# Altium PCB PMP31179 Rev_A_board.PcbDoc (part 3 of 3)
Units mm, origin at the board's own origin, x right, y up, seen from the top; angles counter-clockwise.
Board outline 218.44 x 102.26 mm, 4 copper layers (Top Layer, Mid-Layer 1, Mid-Layer 2, Bottom Layer), stack 1.473 mm thick; 246 components, 120 nets, 592 pads, 115 vias.
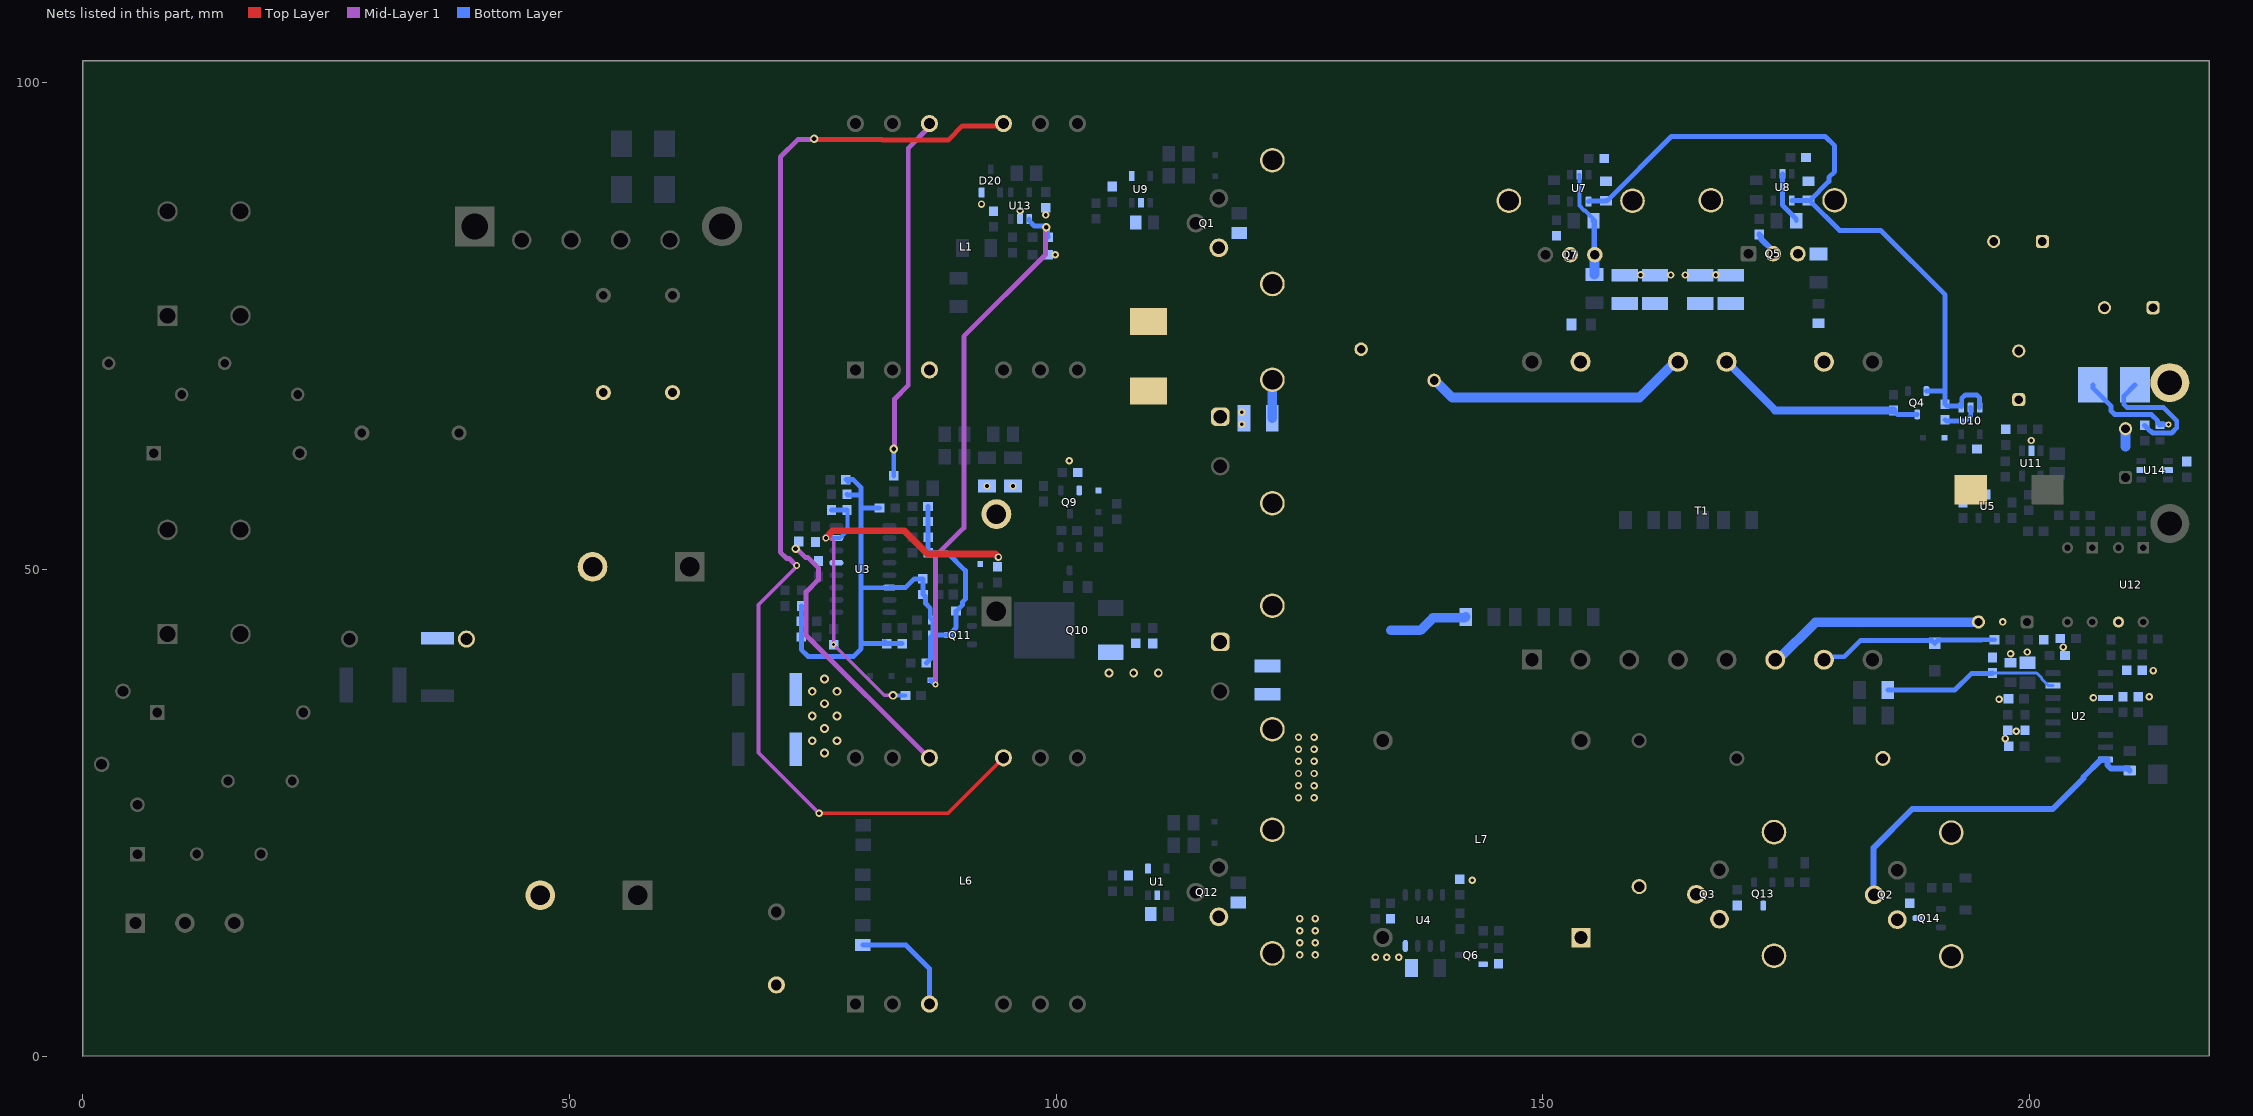
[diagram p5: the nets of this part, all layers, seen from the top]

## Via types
v1: diameter 0.762, hole 0.381, Top Layer to Bottom Layer, 47 vias
v2: diameter 0.9, hole 0.5, Top Layer to Bottom Layer, 18 vias
v3: diameter 0.762, hole 0.381, Top Layer to Bottom Layer, tented bottom, 17 vias
v4: diameter 0.9, hole 0.5, Top Layer to Bottom Layer, tented bottom, 7 vias
v5: diameter 0.6, hole 0.3, Top Layer to Bottom Layer, tented bottom, 5 vias
v6: diameter 0.762, hole 0.381, Top Layer to Bottom Layer, tented both sides, 5 vias
v7: diameter 0.9, hole 0.5, Top Layer to Bottom Layer, tented top, 4 vias
v8: diameter 0.7, hole 0.4, Top Layer to Bottom Layer, tented bottom, 4 vias
v9: diameter 0.6, hole 0.3, Top Layer to Bottom Layer, 4 vias
v10: diameter 0.7, hole 0.4, Top Layer to Bottom Layer, tented top, 1 vias
v11: diameter 0.9, hole 0.5, Top Layer to Bottom Layer, tented both sides, 1 vias
v12: diameter 0.7/0.7/0.7/0.7 (per signal layer), hole 0.4, Top Layer to Bottom Layer, 1 vias
v13: diameter 0.762, hole 0.381, Top Layer to Bottom Layer, tented top, 1 vias

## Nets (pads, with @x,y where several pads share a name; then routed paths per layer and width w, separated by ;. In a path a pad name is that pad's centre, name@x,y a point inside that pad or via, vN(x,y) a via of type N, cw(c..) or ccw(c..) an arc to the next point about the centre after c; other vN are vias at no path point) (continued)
PGND: C3.2 C7.2 C8.2 C15.2 C16.2 C17.2 C18.2 C19.2 C20.2 C21.2 C22.2 C23.2 C24.2 C25.2 C27.2 C28.2 C29.2 C30.1 C31.2 C32.2 C33.2 C34.2 C35.1 C36.2 C37.2 C38.2 C41.2 C43.2 C51.2 C52.2 C58.2 C59.2 C60.2 C62.2 C63.2 C65.2 D14.2 D20.2 L1.9 L6.9 M1.1 M1.2 M2.1 M2.2 M3.1 M3.2 M4.1 M4.2 M5.1 M5.2 M6.1 M6.2 Q1.3 Q2.3 Q6.2 Q9.2 Q10.3 Q11.3 Q12.3 Q14.3 R1.1 R2.1 R3.1 R6.1 R7.1 R8.1 R11.1 R12.1 R14.2 R18.1 R19.1 R32.1 R35.1 R41.2 R45.1 R55.1 R64.1 R76.1 R82.1 R88.2 R89.1 R90.1 RT1.1 T1.6 U1.2 U1.4 U2.11 U3.6 U3.13 U4.4 U9.2 U9.4 U12.3 U13.2 | length 217.7
  Top Layer w0.381: v1(75.634,24.972) 88.883,24.972 L6.9@94.575,30.664
  Top Layer w0.5: v7(75.131,94.256) 75.207,94.179 82.111,94.179 82.14,94.149 88.935,94.149 90.362,95.576 94.336,95.576 L1.9@94.575,95.815
  Mid-Layer 1 w0.381: v12(73.343,50.407) 73.343,50.32 69.422,46.4 69.422,42.294 69.422,31.184 v1(75.634,24.972)
  Mid-Layer 1 w0.5: v12(73.343,50.407) 73.289,50.407 72.543,51.152 72.291,51.152 71.665,51.778 71.665,92.385 73.459,94.179 75.054,94.179 v7(75.131,94.256)
  Bottom Layer w0.381: L6.9@94.205,30.664 L6.9@94.575,30.664
  Bottom Layer w0.5: C29.2@73.818,46.271 73.808,46.261 73.808,44.694 C37.2@73.797,44.684 R11.1@73.797,43.087 73.818,43.067 73.818,41.767 74.498,41.087 79.176,41.087 79.951,41.862 79.951,42.64 ; R41.2@78.386,59.238 R41.2@78.411,59.238 ; C38.2@78.499,57.734 78.56,57.672 79.951,57.672 ; R41.2@78.636,58.988 78.636,59.013 R41.2@78.411,59.238 ; C25.2@81.851,56.316 79.951,56.316 ; C43.2@82.36,42.64 82.585,42.415 C43.2@82.585,42.39 ; R90.1@84.176,42.39 C43.2@82.585,42.39 ; R18.1@86.652,40.416 86.677,40.416 87.067,40.806 87.067,43.04 87.292,43.265 C41.2@87.317,43.265 ; R35.1@86.828,56.469 C33.2@86.828,54.945 86.835,54.938 86.835,53.339 R89.1@86.842,53.332 C21.2@86.842,51.731 86.846,51.735 88.825,51.735 90.66,49.9 90.66,46.966 90.351,46.657 90.351,46.355 89.73,45.733 C15.2@89.705,45.733 89.705,44.032 89.192,43.519 89.192,43.319 89.142,43.269 Q11.3@88.942,43.269 88.94,43.267 87.319,43.267 C41.2@87.317,43.265 ; R41.2@78.411,59.238 79.136,59.238 79.951,58.422 79.951,57.672 ; 79.951,42.64 80.201,42.39 C43.2@82.585,42.39 ; 79.951,42.64 79.951,48.002 ; 79.951,48.002 80.085,48.136 82.843,48.136 U3.6@82.862,48.155 82.881,48.174 84.54,48.174 85.417,49.052 C34.2@86.284,49.052 86.299,49.037 86.299,47.467 C36.2@86.314,47.452 86.339,47.452 86.564,47.227 86.564,46.524 87.053,46.035 87.053,45.035 87.278,44.81 R88.2@87.303,44.81 87.31,44.803 87.31,43.272 C41.2@87.317,43.265 ; 79.951,48.002 79.951,56.316 ; 79.951,56.316 79.951,57.672
  Bottom Layer w1: C7.2@122.196,65.553 122.201,65.557 122.201,69.503 M6.1@122.205,69.508 ; T1.6@173.864,40.744 174.148,40.744 177.981,44.577 C60.2@194.694,44.577 ; C60.2@194.671,44.554 C60.2@194.694,44.577 ; C60.2@194.738,44.621 C60.2@194.694,44.577
  other v1: 132.788,10.187 133.954,10.187 135.173,10.187 125.019,10.414 126.619,10.414 125.019,11.659 126.619,11.659 125.019,12.903 126.619,12.903 125.019,14.148 126.619,14.148 142.742,18.08 124.886,26.564 126.486,26.564 124.886,27.808 126.486,27.808 124.886,29.053 126.486,29.053 124.886,30.297 126.486,30.297 124.886,31.542 126.486,31.542 124.886,32.787 126.486,32.787 197.238,44.621 101.341,61.176
  other v2: 74.93,32.415 76.2,33.685 74.93,34.955 77.47,34.955 76.2,36.225 74.93,37.495 77.47,37.495 76.2,38.765 105.41,39.37 107.95,39.37 110.49,39.37
  other v3: 197.485,32.639 198.628,33.401 196.855,36.684 206.548,36.823 212.287,36.934 212.681,39.628 198.04,41.341 199.76,41.532 203.454,42.037 99.904,82.331
  other v6: 98.922,86.434 96.28,86.852 92.325,87.549
  other v7: 76.2,31.145 77.47,32.415
R_SENSE: pad.1@214.397,69.208 R65.2 R66.1 | length 13.2
  Bottom Layer w0.5: R65.2@210.817,68.98 209.665,67.828 209.665,66.979 210.005,66.639 213.775,66.639 215.108,65.306 215.108,64.564 214.571,64.027 212.663,64.027 212.51,64.18 212.434,64.18 211.812,64.802 R66.1@211.812,64.827
SGND: C12.2 C13.2 C14.2 C44.1 C45.1 C46.2 C48.2 C53.2 C54.2 C55.2 C56.2 C57.2 C67.2 C68.2 C72.2 C73.2 C76.2 C100.2 C101.2 D4.2 M7.1 M7.2 M8.1 M8.2 Q5.3 Q7.3 R50.1 R65.1 R72.1 R78.1 U5.3 U7.2 U8.2 U10.2 U11.2 U14.2 U14.5 | length 32.1
  Bottom Layer w0.4: U7.2@153.723,90.557 153.737,90.543 153.737,87.402 154.235,86.904 154.307,86.904 155.194,86.017 C100.2@155.194,85.852
  Bottom Layer w0.5: U8.2@174.609,90.663 174.609,87.43 176.022,86.017 C101.2@176.022,85.852 ; C55.2@191.309,65.396 191.431,65.274 193.429,65.274 193.944,65.789 193.944,66.634 U10.2@193.929,66.649 ; R65.1@206.497,68.98 206.497,68.665 208.37,66.792 208.37,66.29 208.723,65.936 212.511,65.936 213.163,65.284 213.163,65.052 R78.1@213.388,64.827 213.473,64.912 214.234,64.912 v5(214.249,64.897)
  Bottom Layer w0.6: C100.2@155.194,85.852 155.263,85.783 155.263,82.421 Q7.3@155.333,82.352
  Bottom Layer w1: C45.1@155.276,80.309 155.304,80.337 155.304,82.323 Q7.3@155.333,82.352 ; 209.851,62.626 C76.2@209.851,64.469
  other v1: 200.173,63.262 160.026,80.27 163.138,80.267 164.611,80.267 167.761,80.27
SW: C26.2 L7.1 Q2.2 Q3.3 Q13.3 R44.1 U2.16 | length 35.8
  Bottom Layer w0.6: Q2.2@184.038,16.583 183.973,16.648 183.973,21.429 187.94,25.396 202.362,25.396 205.531,28.565 205.531,28.694 207.311,30.473 U2.16@207.786,30.473 207.98,30.473 207.98,29.918 208.343,29.556 210.087,29.556 C26.2@210.287,29.356
UVLO: D15.1 R75.2 U13.1 | length 55.7
  Mid-Layer 1 w0.5: v9(87.587,38.183) 87.587,51.366 90.505,54.283 90.505,73.969 98.895,82.36 98.895,85.096 v11(98.972,85.173)
  Bottom Layer w0.5: D15.1@87.079,38.638 87.515,38.202 87.568,38.202 v9(87.587,38.183) ; U13.1@97.23,86.025 97.23,85.825 97.755,85.3 98.844,85.3 v11(98.972,85.173) 99.099,85.045 99.099,84.209 R75.2@99.154,84.154
V30V: C8.1 C12.1 C13.1 C14.1 C67.1 C68.1 C72.1 C73.1 L4.1 Q4.3 R62.2 T1.12 T1.13 | length 49.1
  Bottom Layer w0.5: R62.2@186.012,66.354 186.012,66.329 186.237,66.104 186.262,66.104 186.43,65.936 Q4.3@188.451,65.936
  Bottom Layer w0.8: T1.12@168.864,71.344 T1.12@168.864,71.344 173.852,66.354 R62.2@186.012,66.354
  Bottom Layer w1: C8.1@138.821,69.439 138.929,69.439 140.677,67.691 159.927,67.691 163.58,71.344 T1.13@163.864,71.344
VAC: C5.1 C61.1 D100.2 L1.3 L2.2 L6.3 R23.2 R91.2 | length 11.5
  Bottom Layer w0.5: R23.2@80.137,11.43 84.549,11.43 86.975,9.004 L6.3@86.975,5.364
VCR: C22.1 C40.2 U2.7 | length 18.3
  Bottom Layer w0.3: C22.1@196.182,39.378 196.186,39.382 200.72,39.382 201.241,38.861 201.241,38.764 201.911,38.093 U2.7@202.386,38.093
  Bottom Layer w0.5: C40.2@185.423,37.638 192.333,37.638 194.009,39.315 196.119,39.315 C22.1@196.182,39.378
VD1: Q7.2 R53.1 R100.2 T1.15 | length 0.3
  Bottom Layer w0.5: Q7.2@152.793,82.352 Q7.2@152.793,82.649
VD2: Q5.2 R52.1 R101.2 T1.10 | length 2.6
  Bottom Layer w0.6: R101.2@172.212,84.417 172.387,84.242 172.387,83.988 173.652,82.722 Q5.2@173.652,82.452
VDD: C46.1 C48.1 C55.1 Q4.2 U7.4 U8.4 U10.1 U10.3 | length 73.7
  Bottom Layer w0.5: U7.4@154.673,87.807 154.719,87.854 156.418,87.854 C46.1@156.464,87.9 156.589,87.9 163.177,94.488 178.995,94.488 179.959,93.524 179.959,90.868 179.377,90.287 179.377,89.883 C48.1@177.401,87.907 ; U8.4@175.559,87.913 175.562,87.91 177.273,87.91 C48.1@177.276,87.907 C48.1@177.401,87.907 ; Q4.2@189.401,68.336 189.418,68.354 191.291,68.354 191.309,68.336 ; U10.3@194.879,66.649 194.865,66.663 194.865,67.643 194.572,67.936 193.379,67.936 193.029,67.586 193.029,66.823 192.979,66.773 192.929,66.823 191.483,66.823 C55.1@191.309,66.996 191.309,68.336 ; C48.1@177.401,87.907 180.464,84.844 184.681,84.844 191.309,78.216 191.309,68.336
Vpfc: C1A.2 C1B.2 C1C.2 C2.1 C7.1 C65.1 D1.1 D5.1 D100.1 Q3.2 R20.2 R43.2 R87.2 | length 8.3
  Bottom Layer w1: 134.359,43.761 137.4,43.761 138.689,45.05 141.971,45.05 R43.2@142.066,45.145
  other v1: 92.888,58.583 95.555,58.583 119.046,64.921 119.046,66.173
VREF: C38.1 D2.1 R15.1 R16.2 R37.2 R39.2 U3.15 | length 46.6
  Top Layer w0.7: v8(76.327,53.243) 77.076,53.992 84.363,53.992 86.759,51.596 93.745,51.596 94.059,51.283 v3(94.063,51.283)
  Mid-Layer 1 w0.381: v8(76.327,53.243) 76.331,53.239 76.869,53.239 77.135,52.973 v9(77.135,42.287) 82.339,37.084 v4(83.219,37.084)
  Bottom Layer w0.381: v8(76.327,53.243) 76.331,53.239 77.408,53.239 U3.15@77.412,53.235 ; v4(83.219,37.084) 83.233,37.07 84.488,37.07 R16.2@84.502,37.056
  Bottom Layer w0.4: U3.15@77.412,53.235 77.783,53.235 78.54,53.992 78.54,56.093 C38.1@78.499,56.134
  Bottom Layer w0.5: R39.2@76.899,56.134 C38.1@78.499,56.134
X: D11.2 R9.2 T1.7 | length 18.6
  Bottom Layer w0.5: T1.7@178.864,40.744 179.161,41.04 180.936,41.04 182.602,42.706 189.961,42.706 D11.2@190.246,42.421 190.596,42.771 195.073,42.771 195.096,42.794 R9.2@196.398,42.794
ZCD_A: L6.10 R24.2 | length 28.6
  Mid-Layer 1 w0.5: v4@73.139,52.137 73.337,52.137 74.218,51.256 74.477,51.256 75.565,50.168 75.565,48.943 74.293,47.671 74.293,43.261 86.89,30.664 L6.10@86.975,30.664
  other v4: 73.229,52.137
ZCD_B: L1.10 R26.2 | length 37.7
  Mid-Layer 1 w0.5: v2(83.306,62.383) 83.383,62.46 83.383,67.512 84.801,68.93 84.801,93.302 86.975,95.476 L1.10@86.975,95.815
  Bottom Layer w0.5: v2(83.306,62.383) 83.308,62.382 83.308,59.635 R26.2@83.31,59.633
pads on no net: D20.3 H1.0 H2.0 H3.0 H4.0 H5.0 H6.0 H7.1 H7.2 L1.1 L1.2 L1.5 L1.6 L1.7 L1.8 L1.11 L1.12 L6.1 L6.2 L6.5 L6.6 L6.7 L6.8 L6.11 L6.12 L7.7 L7.14 T1.1 T1.8 T1.9 T1.16 U4.2 U4.5 U4.6 U10.4

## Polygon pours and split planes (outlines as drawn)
V30V on Top Layer "TOP_LAYER_V30V_P064" (solid, remove dead copper, pour order 64): 161.794,73.431 170.408,73.431 173.959,69.88 206.49,69.88 210.651,74.041 210.651,79.063 208.688,81.026 200.256,81.026 199.105,82.177 199.105,96.108 202.057,99.06 214.884,99.06 216.789,97.155 216.789,72.662 216.015,71.889 213.545,71.889 211.957,70.3 211.957,67.746 209.116,64.905 199.744,64.905 195.938,61.099 195.938,56.837 195.228,56.127 189.498,56.127 188.079,57.546 173.309,57.546 161.794,69.061
SGND on Top Layer "TOP_LAYER_SGND_P063" (solid, remove dead copper, pour order 63): 142.24,78.826 169.616,78.826 177.273,71.169 205.732,71.169 208.858,74.295 208.858,78.466 208.039,79.285 199.043,79.285 197.851,80.477 197.851,96.058 194.848,99.06 145.923,99.06 142.24,95.377
30V on Top Layer "TOP_LAYER_30V_P059" (solid, remove dead copper, pour order 59): 216.015,51.181 201.214,51.181 200.154,52.241 200.154,60.019 200.729,60.594 216.026,60.594 216.789,59.831 216.789,51.955
PGND on Top Layer "TOP_LAYER_PGND_P042" (solid, remove dead copper, pour order 42): 133.604,75.591 132.275,74.262 132.275,67.163 133.604,65.834 133.604,32.425 138.221,27.808 178.568,27.808 182.614,31.854 186.138,31.854 187.437,30.556 188.403,30.556 190.86,28.098 197.299,28.098 199.665,25.732 199.665,4.046 197.529,1.909 116.101,1.905 116.101,15.203 116.495,15.598 119.809,15.598 120.858,16.648 120.858,45.572 119.445,46.986 116.123,46.986 114.831,48.278 114.831,56.008 116.382,57.559 121.406,57.559 121.406,77.23 115.695,82.941 115.695,83.555 116.625,84.484 121.485,84.484 121.485,99.06 130.937,99.06 133.604,96.393
PGND on Top Layer "TOP_LAYER_PGND_P039" (solid, remove dead copper, pour order 39): 183.763,29.465 199.371,29.465 201.784,27.052 201.784,4.875 204.089,2.57 213.274,2.57 216.916,6.212 216.916,44.579 216.059,45.436 184.501,45.436 183.763,44.698
VAC on Top Layer "TOP_LAYER_VAC_P019" (solid, remove dead copper, pour order 19): 111.379,73.182 94.768,73.182 88.687,67.1 87.818,67.1 85.299,69.619 85.299,76.921 88.276,79.897 109.947,79.897 111.379,78.465
Vpfc on Top Layer "TOP_LAYER_VPFC_P018" (solid, remove dead copper, pour order 18): 80.476,61.1 87.491,61.1 96.327,69.935 117.86,69.935 119.855,67.94 119.855,64.558 118.455,63.158 114.831,63.158 112.44,60.767 112.44,47.078 114.355,45.163 117.66,45.163 119.046,43.777 119.046,41.506 117.727,40.188 114.014,40.188 106.299,40.188 105.122,41.365 105.122,46.887 98.905,53.104 87.428,53.104 83.935,56.596 80.412,56.596
Vpfc on Top Layer "TOP_LAYER_VPFC_P017" (solid, remove dead copper, pour order 17): 51.501,14.73 53.213,16.442 53.213,23.398 56.134,26.319 56.134,51.726 59.62,55.212 84.237,55.212 86.369,53.081 98.353,53.081 99.415,54.142 99.415,59.751 98.065,61.1 59.373,61.1 45.37,47.097 45.37,15.842 46.482,14.73
NetC1A_1 on Top Layer "TOP_LAYER_NETC1A_1_P015" (solid, remove dead copper, pour order 15): 54.737,21.366 58.166,24.795 58.166,50.743 60.579,53.081 82.415,53.081 85.306,50.19 99.459,50.19 102.399,47.25 102.399,41.133 99.322,38.056 83.09,38.056 75.005,29.97 75.107,14.096 55.656,14.096 54.737,15.016
VAC on Top Layer "TOP_LAYER_VAC_P011" (solid, remove dead copper, pour order 11): 75.563,72.19 75.563,79.882 87.847,79.882 89.527,78.201 89.645,73.694 89.645,67.439 85.227,63.022 59.361,63.022 43.18,46.841 43.18,16.54 46.228,13.492 87.349,13.492 90.551,10.29 90.551,5.999 86.614,2.062 39.116,2.062 30.89,10.287 30.89,53.145 49.936,72.19
NetC10_2 on Top Layer "TOP_LAYER_NETC10_2_P005" (solid, remove dead copper, pour order 5): 13.259,51.984 18.307,51.984 24.037,57.714 24.037,75.348 20.542,78.842 14.313,78.842 12.827,77.356 12.827,75.334 15.791,72.37 15.791,65.143 13.259,62.612
NetC10_1 on Top Layer "TOP_LAYER_NETC10_1_P004" (solid, remove dead copper, pour order 4): 11.207,51.984 5.76,51.984 1.473,56.272 1.473,75.87 4.445,78.842 9.622,78.842 10.711,77.754 10.711,73.956 7.864,71.109 7.864,65.714 11.207,62.371
NetC9_2 on Top Layer "TOP_LAYER_NETC9_2_P002" (solid, remove dead copper, pour order 2): 17.593,27.507 13.208,23.122 13.274,20.416 8.509,15.651 8.509,12.473 9.268,11.714 10.803,11.714 16.793,17.704 16.793,20.757 24.138,28.102 24.138,43.865 16.793,51.211 2.216,51.211 0.946,49.941 0.946,36.88 2,35.826 5.173,35.826 6.207,36.86 6.207,46.104 6.858,46.755 10.093,46.755 17.593,39.255
NetC6_1 on Top Layer "TOP_LAYER_NETC6_1_P001" (solid, remove dead copper, pour order 1): 1.079,26.763 2.921,24.922 7.508,24.922 12.349,29.763 12.349,42.321 9.343,45.327 7.684,45.327 7.176,44.819 7.176,36.484 1.079,30.388
NetF1_1 on Top Layer "TOP_LAYER_NETF1_1_P000" (solid, remove dead copper, pour order 0): 6.604,11.714 3.81,11.714 2.159,13.365 2.159,21.239 3.175,22.255 6.858,22.255 7.493,21.62 7.493,12.603
SGND on Mid-Layer 2 "MID-LAYER_2_SGND_P044" (solid, remove dead copper, pour order 44): 187.374,58.21 187.374,61.24 184.132,64.473 184.132,69.909 201.57,69.909 208.352,63.128 210.446,63.128 211.45,62.123 211.45,61.917 216.789,61.917 216.789,51.955 216.015,51.181 190.5,51.181 189.736,51.945 189.736,55.848
SGND on Mid-Layer 2 "MID-LAYER_2_SGND_P057" (solid, remove dead copper, pour order 57): 202.484,71.12 209.705,63.899 215.528,63.899 216.789,65.16 216.789,95.25 212.979,99.06 147.986,99.06 143.681,94.755 143.7,62.897 180.367,62.897 182.021,64.551 182.021,69.88 183.261,71.12
PGND on Mid-Layer 2 "MID-LAYER_2_PGND_P014" (solid, remove dead copper, pour order 14): 133.731,75.596 132.123,73.988 132.085,73.988 132.085,67.353 133.731,65.834 133.731,61.244 146.487,48.488 181.428,48.488 182.614,47.302 182.614,36.089 191.023,27.679 198.964,27.679 201.278,25.365 201.278,6.446 197.529,2.697 32.766,2.697 26.289,9.174 26.289,92.232 33.274,99.217 130.699,99.217 133.731,96.185
PGND on Mid-Layer 2 "MID-LAYER_2_PGND_P038" (solid, remove dead copper, pour order 38): 183.763,29.465 199.371,29.465 201.784,27.052 201.784,4.875 204.089,2.57 213.274,2.57 216.916,6.212 216.916,44.579 216.059,45.436 184.501,45.436 183.763,44.698
EARTH on Mid-Layer 2 "MID-LAYER_2_EARTH_P003" (solid, remove dead copper, pour order 3): 1.171,11.714 1.171,79.16 24.13,79.16 24.13,11.714
Vpfc on Bottom Layer "BOTTOM_LAYER_VPFC_P066" (solid, remove dead copper, pour order 66): 115.906,63.928 120.028,63.928 120.163,64.064 120.163,66.983 119.855,67.291 115.892,67.291 115.606,67.005 115.606,64.228
PGND on Bottom Layer "BOTTOM_LAYER_PGND_P065" (solid, remove dead copper, pour order 65): 120.015,37.973 123.544,37.973 126.956,34.561 126.956,31.333 126.415,30.792 120.846,30.792 120.015,31.623
SGND on Bottom Layer "BOTTOM_LAYER_SGND_P062" (solid, remove dead copper, pour order 62): 210.754,63.705 209.564,63.705 202.149,71.12 196.728,71.12 194.879,72.969 194.879,95.443 194.818,95.504 198.374,99.06 206.011,99.06 208.957,96.114 208.957,71.685 208.039,70.768 208.039,67.246 209.349,65.936 210.824,65.936
R_SENSE on Bottom Layer "BOTTOM_LAYER_R_SENSE_P060" (solid, remove dead copper, pour order 60): 209.296,67.183 215.506,67.183 216.614,68.29 216.614,70.218 215.407,71.425 209.296,71.425
SGND on Bottom Layer "BOTTOM_LAYER_SGND_P058" (solid, remove dead copper, pour order 58): 187.369,58.224 187.369,61.253 184.127,64.487 184.127,69.923 201.566,69.923 208.347,63.141 210.441,63.141 211.445,62.137 211.445,61.931 216.784,61.931 216.784,51.968 216.011,51.195 190.496,51.195 189.731,51.959 189.731,55.862
VD2 on Bottom Layer "BOTTOM_LAYER_VD2_P056" (solid, remove dead copper, pour order 56): 176.775,75.885 175.492,77.169 175.492,78.527 175.006,79.013 175.006,82.348 174.114,83.24 173.135,83.24 172.903,83.008 172.903,72.674 175.667,69.909 180.194,69.909 180.194,74.712 179.021,75.885
NetC44_2 on Bottom Layer "BOTTOM_LAYER_NETC44_2_P055" (solid, remove dead copper, pour order 55): 179.414,76.708 177.502,76.708 177.216,76.994 177.216,80.06 177.408,80.252 179.29,80.252 179.483,80.059 179.483,76.777
SGND on Bottom Layer "BOTTOM_LAYER_SGND_P054" (solid, remove dead copper, pour order 54): 176.543,91.255 176.519,91.279 176.519,92.806 177.741,92.806 178.297,92.249 178.364,90.95 178.612,90.702 178.612,89.118 177.983,88.489 175.138,88.489 175.138,87.501 175.492,87.148 176.7,87.148 176.7,84.353 177.174,83.88 178.93,83.88 179.483,83.327 179.483,81.47 175.785,81.47 175.414,81.841 175.414,84.639 174.109,85.944 174.109,91.142 174.356,91.388 175.109,91.388 175.109,90.357 175.376,90.089 176.009,90.089 176.009,90.722
SGND on Bottom Layer "BOTTOM_LAYER_SGND_P053" (solid, remove dead copper, pour order 53): 157.038,79.527 170.635,79.527 170.885,79.777 170.885,80.851 170.635,81.101 157.163,81.101 157.038,80.977
V30V on Bottom Layer "BOTTOM_LAYER_V30V_P052" (solid, remove dead copper, pour order 52): 157.038,78.074 157.038,73.988 161.117,69.909 169.932,69.909 170.853,70.831 170.853,78.041 170.885,78.074
SGND on Bottom Layer "BOTTOM_LAYER_SGND_P051" (solid, remove dead copper, pour order 51): 155.784,90.278 155.784,92.705 156.788,92.705 156.788,90.487 157.214,90.487 157.214,88.925 156.996,88.707 154.547,88.707 154.223,88.383 154.223,87.469 154.824,86.868 155.776,86.868 155.776,85.209 154.452,85.209 154.452,86.37 154.259,86.37 153.326,87.302 153.326,91.137 153.471,91.282 154.039,91.282 154.223,91.099 154.223,89.837 154.377,89.682 155.188,89.682
NetC100_1 on Bottom Layer "BOTTOM_LAYER_NETC100_1_P050" (solid, remove dead copper, pour order 50): 150.909,85.209 151.925,85.209 152.298,84.836 153.897,84.836 153.951,84.889 153.951,86.502 153.351,87.102 153.351,88.383 152.352,88.383 152.173,88.203 152.173,87.082 151.73,86.64 151.12,86.64 150.909,86.429
VD1 on Bottom Layer "BOTTOM_LAYER_VD1_P049" (solid, remove dead copper, pour order 49): 152.586,69.571 151.733,70.424 151.733,82.525 150.691,83.566 150.691,84.629 150.909,84.846 151.966,84.846 153.997,82.815 153.997,82.106 153.997,74.041 155.272,72.766 155.46,72.766 155.46,69.909 155.121,69.571
PGND on Bottom Layer "BOTTOM_LAYER_PGND_P041" (solid, remove dead copper, pour order 41): 183.89,29.216 196.301,29.216 198.616,31.531 198.616,36.258 187.771,36.258 183.842,32.329
PGND on Bottom Layer "BOTTOM_LAYER_PGND_P040" (solid, remove dead copper, pour order 40): 216.916,36.258 206.847,36.258 203.355,32.766 199.209,32.766 198.659,32.216 198.659,31.129 196.702,31.129 191.275,36.557 191.275,45.436 216.059,45.436 216.916,44.579
NetC2_2 on Bottom Layer "BOTTOM_LAYER_NETC2_2_P037" (solid, remove dead copper, pour order 37): 159.056,29.717 169.997,29.717 170.696,30.416 170.696,40.572 169.293,41.974 162.563,41.974 162.279,41.69 162.279,36.126 159.008,32.855
NetL7_6 on Bottom Layer "BOTTOM_LAYER_NETL7_6_P036" (solid, remove dead copper, pour order 36): 153.39,30.842 155.199,30.842 160.449,36.092 160.449,40.744 159.219,41.974 153.409,41.974 152.226,40.792 152.226,31.876 153.226,30.876
PGND on Bottom Layer "BOTTOM_LAYER_PGND_P035" (solid, remove dead copper, pour order 35): 187.94,12.744 189.006,13.811 189.006,15.695 188.4,16.302 186.849,16.302 185.462,14.915 185.203,14.656 185.203,13.601 186.06,12.744
SW on Bottom Layer "BOTTOM_LAYER_SW_P034" (solid, remove dead copper, pour order 34): 164.963,13.711 ccw(c164.963,16.251) 166.759,14.455 167.897,15.593 cw(c169.178,14.312) 169.178,16.124 180.414,16.124 ccw(c180.414,18.381) 182.01,16.785 183.034,17.809 cw(c183.689,17.154) 183.689,18.08 184.214,18.08 cw(c184.214,17.073) 185.222,17.073 cw(c182.855,17.073) 184.528,15.4 183.116,13.988 cw(c181.32,15.784) 181.32,13.244 169.828,13.244 ccw(c169.828,12.863) 169.559,13.132 167.812,11.386 cw(c166.016,13.182) 166.016,10.642 152.819,10.642 cw(c152.819,11.492) 151.969,11.492 151.969,12.135 cw(c153.545,12.135) 153.545,13.711
PGND on Bottom Layer "BOTTOM_LAYER_PGND_P033" (solid, remove dead copper, pour order 33): 134.602,19.399 126.956,19.399 120.685,13.129 120.685,8.316 123.667,5.334 134.874,5.334
PGND on Bottom Layer "BOTTOM_LAYER_PGND_P032" (solid, remove dead copper, pour order 32): 130.375,8.559 133.6,5.334 145.434,5.334 147.571,7.47 147.571,14.536 142.688,19.419 132.253,19.419 130.375,17.542
Vpfc on Bottom Layer "BOTTOM_LAYER_VPFC_P031" (solid, remove dead copper, pour order 31): 125.103,38.637 118.923,38.637 115.54,42.019 115.54,44.283 135.325,44.283 137.166,42.442 157.976,21.632 162.897,21.632 167.116,17.413 167.116,15.983 166.316,15.183 148.557,15.183
PGND on Bottom Layer "BOTTOM_LAYER_PGND_P030" (solid, remove dead copper, pour order 30): 105.033,94.149 89.604,94.149 84.644,89.189 84.644,75.703 86.652,73.694 100.275,73.694 105.046,78.465 105.033,78.478
PGND on Bottom Layer "BOTTOM_LAYER_PGND_P029" (solid, remove dead copper, pour order 29): 119.906,85.212 117.454,85.212 115.135,82.893 113.778,82.893 112.141,84.53 112.141,86.736 113.862,88.458 114.89,89.486 114.89,95.379 114.299,95.97 106.368,95.97 102.727,92.328 102.727,83.429 105.291,80.865 118.358,80.865 119.906,82.413
PGND on Bottom Layer "BOTTOM_LAYER_PGND_P027" (solid, remove dead copper, pour order 27): 97.343,60.61 97.343,52.306 99.459,50.19 108.066,50.19 110.614,52.738 110.614,58.643 107.435,61.823 98.296,61.823 97.438,60.965
NetC63_1 on Bottom Layer "BOTTOM_LAYER_NETC63_1_P026" (solid, remove dead copper, pour order 26): 110.648,43.519 107.414,43.519 106.695,44.238 104.792,44.238 102.738,46.292 102.738,48.799 103.125,49.185 107.23,49.185 110.648,45.767
PGND on Bottom Layer "BOTTOM_LAYER_PGND_P025" (solid, remove dead copper, pour order 25): 103.684,43.187 110.51,43.187 111.835,41.862 111.835,39.513 110.973,38.65 104.427,38.65 103.355,39.722 103.355,42.858
PGND on Bottom Layer "BOTTOM_LAYER_PGND_P023" (solid, remove dead copper, pour order 23): 120.361,11.104 108.882,11.104 104.895,15.091 104.895,21.096 107.218,23.419 112.553,23.419 114.199,21.773 114.199,19.919 112.553,18.272 112.553,15.85 113.524,14.88 116.098,14.88 117.742,16.524 120.361,16.524
VAC on Bottom Layer "BOTTOM_LAYER_VAC_P022" (solid, remove dead copper, pour order 22): 40.606,41.389 35.242,41.389 34.163,42.468 34.163,43.822 35.041,44.7 39.904,44.7 40.87,43.734 40.87,41.652
NetL8_2 on Bottom Layer "BOTTOM_LAYER_NETL8_2_P021" (solid, remove dead copper, pour order 21): 31.877,36.247 38.205,36.247 38.399,36.44 38.399,38.555 36.949,40.005 31.812,40.005 31.667,39.86 31.667,36.444 31.871,36.241
VREF on Bottom Layer "BOTTOM_LAYER_VREF_P020" (solid, remove dead copper, pour order 20): 91.879,50.247 92.396,49.73 94.43,49.73 94.43,51.596 94.248,51.778 92.21,51.778 91.877,51.444
NetC1A_1 on Bottom Layer "BOTTOM_LAYER_NETC1A_1_P016" (solid, remove dead copper, pour order 16): 102.039,38.51 100.528,36.999 92.571,36.999 91.422,38.148 91.422,46.697 92.044,47.319 102.021,47.319
PGND on Bottom Layer "BOTTOM_LAYER_PGND_P013" (solid, remove dead copper, pour order 13): 82.3,47.777 83.765,47.777 85.827,45.715 85.827,40.065 89.888,40.065 91.713,41.89 91.713,53.807 88.162,57.358 85.04,57.358 84.201,56.52 84.201,49.145 83.63,48.574 83.615,48.59 82.36,48.59
PGND on Bottom Layer "BOTTOM_LAYER_PGND_P012" (solid, remove dead copper, pour order 12): 70.29,31.434 72.13,29.594 75.634,29.594 77.875,31.834 77.875,37.804 81.711,41.64 84.901,41.64 84.901,42.79 84.651,43.04 81.726,43.04 81.101,43.665 81.101,54.833 81.86,55.591 82.436,55.591 82.436,59.215 80.772,60.879 74.853,60.879 70.29,56.316
CS on Bottom Layer "BOTTOM_LAYER_CS_P010" (solid, remove dead copper, pour order 10): 48.459,67.091 48.459,47.281 55.88,39.86 68.58,39.86 68.58,29.367 52.07,29.367 41.529,39.908 41.529,46.004 35.179,52.354 35.179,62.735 40.005,67.561
CS on Bottom Layer "BOTTOM_LAYER_CS_P009" (solid, remove dead copper, pour order 9): 35.179,62.808 52.965,80.594 56.198,80.594 58.031,82.427 58.031,84.202 58.959,85.13 61.082,85.13 62.23,83.981 62.23,76.56 58.925,73.255 54.559,73.255 42.668,61.364 36.059,61.364 35.179,62.243
NetC4_1 on Bottom Layer "BOTTOM_LAYER_NETC4_1_P008" (solid, remove dead copper, pour order 8): 25.867,36.44 27.831,36.44 32.766,41.375 32.766,63.149 47.244,77.627 47.244,83.763 45.466,85.541 43.939,85.541 24.435,66.036 24.435,37.872
NetD3_2 on Mid-Layer 1 "MID-LAYER_1_NETD3_2_P006" (solid, remove dead copper, pour order 6): 5.093,88.227 5.093,83.382 8.537,79.938 24.089,79.938 26.67,77.356 50.149,77.356 52.07,79.278 52.07,83.85 50.165,85.755 48.509,85.755 47.498,84.744 47.498,82.041 46.64,81.183 27.565,81.183 25.097,83.651 12.43,83.651 10.581,85.501 10.581,87.505 9.156,88.93 6.223,88.93
NetD3_3 on Mid-Layer 1 "MID-LAYER_1_NETD3_3_P007" (solid, remove dead copper, pour order 7): 24.565,84.866 29.256,89.557 49.577,89.557 52.629,86.505 52.629,84.577 54.356,82.85 56.15,82.85 56.769,83.469 56.769,89.311 52.324,93.756 17.377,93.756 13.567,89.946 13.567,86.056 14.757,84.866

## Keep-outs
Keep-Out Layer:
  text ".Layer_Name" at 14.275,-23.427 h1.52

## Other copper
Top Layer:
  pour cut-out: 183.267,18.467 182.919,18.281 182.614,18.031 182.364,17.726 182.178,17.377 182.063,17 182.024,16.607 182.063,16.214 182.178,15.836 182.364,15.488 182.614,15.183 182.919,14.932 183.267,14.746 183.645,14.631 184.038,14.593 184.431,14.631 184.784,14.727 185.157,14.932 185.462,15.183 185.713,15.488 185.899,15.836 186.013,16.214 186.052,16.607 186.013,17 185.899,17.377 185.672,17.775 185.298,18.182 185.108,18.307 184.75,18.485 184.431,18.582 184.038,18.621 183.645,18.582
  text ".Layer_Name" at 14.275,-23.427 h1.52
Bottom Layer:
  text ".Layer_Name" at 14.275,-23.427 h1.52

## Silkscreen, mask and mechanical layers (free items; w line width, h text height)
Top Overlay:
  text "'.PCB_LAYOUT'.PCB_Rev" at 5.402,3.048 h2
  text ".Layer_Name" at 14.275,-23.427 h1.52
Bottom Overlay:
  lines w0.3: 84.752,35.306 84.035,36.015 ; 85.04,36.015 84.035,36.015 ; 91.767,32.893 84.035,36.015
  text ".Layer_Name" at 14.275,-23.427 h1.52
Top Paste:
  text ".Layer_Name" at 14.275,-23.427 h1.52
Bottom Paste:
  text ".Layer_Name" at 14.275,-23.427 h1.52
Top Solder:
  text ".Layer_Name" at 14.275,-23.427 h1.52
  text ".Layer_Name" at 14.275,-23.427 h1.52
Bottom Solder:
  text ".Layer_Name" at 14.275,-23.427 h1.52
Drill Guide:
  text ".Layer_Name" at 14.275,-23.427 h1.52
M1 Board Outline:
  the board outline again, w0.8
  text ".Layer_Name" at 14.275,-23.427 h1.52
M2 Board Dimensions:
  rectangle: -0.381,-8.606 2.794,-5.431
  rectangle: 2.794,-11.781 12.319,-8.606
  lines w0.178: -0.381,-8.606 25.019,-8.606 ; 2.794,-11.781 2.794,-5.431 ; 5.969,-11.781 5.969,-5.431 ; 12.319,-11.781 12.319,-5.431 ; 18.669,-11.781 18.669,-5.431 ; -0.381,-11.781 25.019,-11.781 25.019,-5.431 -0.381,-5.431 -0.381,-11.781
  text "'.Print_Date' '.Print_Time'" at 2.794,105.061 h2
  text ".Layer_Name" at 14.275,-23.427 h1.52
M3 3D STEP Top:
  text ".Layer_Name" at 14.275,-23.427 h1.52
M4 3D STEP Bottom:
  text ".Layer_Name" at 14.275,-23.427 h1.52
M5 Assembly Top:
  lines w0.254: -7.798,-25.248 159.842,-25.248 ; -7.798,-20.083 159.893,-20.083 ; -7.798,-14.918 -7.798,-30.412 93.929,-30.412 159.893,-30.412 159.893,-14.918 -7.785,-14.918 -7.785,-30.412 32.233,-30.412 ; 54.813,-30.412 54.813,-14.918 ; 86.995,-20.083 86.995,-14.918 ; 107.218,43.187 107.24,43.21 107.41,43.21 ; 108.331,-20.083 108.331,-14.918 ; 124.13,-30.577 124.13,-25.425
  text "COMPONENTS MARKED 'DNP' SHOULD NOT BE POPULATED." at 28.918,-9.711 h1.52
  text "ASSEMBLY VARIANT:" at 28.905,-12.645 h1.52
  text ".VariantName" at 55.22,-12.645 h1.52
  text "PCB VIEWED FROM TOP SIDE" at -6.185,-18.275 h1.52
  text "BOARD #:" at 56.718,-18.275 h1.52
  text ".PRJ_Number" at 70.574,-18.275 h1.52
  text "REV:" at 92.024,-18.275 h1.52
  text ".PCB_Rev" at 99.428,-18.275 h1.52
  text "SVN REV:" at 113.309,-18.275 h1.52
  text ".VersionControl_RevNumber" at 126.162,-18.275 h1.52
  text "TID #:" at 56.718,-23.44 h1.52
  text ".TID" at 70.574,-23.44 h1.52
  text "PLOT NAME =" at -6.185,-28.655 h1.52
  text ".plot_File_Name" at 14.275,-28.655 h1.52
  text "GENERATED    :" at 56.769,-28.655 h1.52
  text ".Print_Date" at 78.854,-28.655 h1.52
  text ".Print_Time" at 97.371,-28.655 h1.52
  text "TEXAS INSTRUMENTS" at 129.489,-28.655 h1.52
M6 Assembly Bottom:
  lines w0.254: -7.81,-20.096 159.88,-20.096 ; -7.76,-25.26 159.88,-25.26 ; 27.953,-30.59 27.953,-25.438 ; 43.752,-20.096 43.752,-14.931 ; 65.087,-20.096 65.087,-14.931 ; 97.269,-30.425 97.269,-14.931 ; 119.85,-30.425 159.868,-30.425 159.868,-14.931 -7.81,-14.931 -7.81,-30.425 58.153,-30.425 159.88,-30.425 159.88,-14.931
  text "COMPONENTS MARKED 'DNP' SHOULD NOT BE POPULATED." at 154.61,-9.699 h1.52
  text ".VariantName" at 128.092,-12.645 h1.52
  text "ASSEMBLY VARIANT:" at 154.483,-12.645 h1.52
  text ".VersionControl_RevNumber" at 25.921,-18.288 h1.52
  text "SVN REV:" at 38.773,-18.288 h1.52
  text ".PCB_Rev" at 52.654,-18.288 h1.52
  text "REV:" at 60.058,-18.288 h1.52
  text ".PRJ_Number" at 81.509,-18.288 h1.52
  text "BOARD #:" at 95.364,-18.288 h1.52
  text "PCB VIEWED FROM BOTTOM SIDE" at 158.267,-18.288 h1.52
  text ".TID" at 81.509,-23.453 h1.52
  text "TID #:" at 95.364,-23.453 h1.52
  text "TEXAS INSTRUMENTS" at 22.593,-28.668 h1.52
  text ".Print_Time" at 54.712,-28.668 h1.52
  text ".Print_Date" at 73.228,-28.668 h1.52
  text "GENERATED    :" at 95.313,-28.668 h1.52
  text ".plot_File_Name" at 137.808,-28.668 h1.52
  text "PLOT NAME =" at 158.267,-28.668 h1.52
M9 Title Sheet:
  drawing of 57 lines, arcs and shapes, not listed
  text "1" at 18.411,202.506 h1.78
  text "2" at 81.801,202.506 h1.78
  text "3" at 145.03,202.506 h1.78
  text "4" at 208.699,202.506 h1.78
  text "5" at 272.174,202.506 h1.78
  text "6" at 335.801,202.506 h1.78
  text "A" at -10.96,173.474 h1.78
  text "A" at 364.96,173.474 h1.78
  text "B" at -10.96,113.022 h1.78
  text "B" at 364.96,113.022 h1.78
  text "C" at -10.96,52.697 h1.78
  text "C" at 364.96,52.697 h1.78
  text "PROJECT TITLE:" at 287.744,5.427 h1.14
  text ".PRJ_Title" at 289.014,2.041 h1.78
  text "DESIGNED FOR:" at 287.744,-2.218 h1.14
  text ".PRJ_Customer" at 289.014,-5.774 h1.78
  text "D" at -10.96,-7.501 h1.78
  text "D" at 364.96,-7.501 h1.78
  text "FILE NAME:" at 287.744,-9.838 h1.14
  text ".PCB_File_Name_No_Path" at 289.014,-12.886 h1.78
  text "Texas Instruments (TI) and/or its licensors do not warrant the accuracy or completeness of this specification" at 161.519,-16.997 h1.14
  text "ENGINEER:" at 287.744,-17.204 h1.14
  text "LAYOUT BY:" at 325.971,-17.204 h1.14
  text "or any information contained therein. TI and/or its licensors do not warrant that this design will meet" at 160.376,-19.859 h1.14
  text ".PRJ_Engineer" at 289.014,-21.141 h1.78
  text ".PCB_Layout" at 327.254,-21.141 h1.78
  text "the specifications, will be suitable for your application or fit for any particular purpose, or will operate in" at 160.376,-22.72 h1.14
  text ".Layer_Name" at 14.275,-23.427 h1.52
  text "ALTIUM DESIGNER VERSION:" at 325.971,-25.078 h1.14
  text "an implementation. TI and/or its licensors do not warrant that the design is production worthy. You should" at 160.376,-25.582 h1.14
  text "completely validate and test your design implementation to confirm the system functionality for your application." at 161.519,-28.444 h1.14
  text ".print_Scale" at 289.014,-28.465 h1.78
  text ".Application_BuildNumber" at 327.254,-28.465 h1.78
  text "1" at 18.411,-33.714 h1.78
  text "2" at 81.801,-33.714 h1.78
  text "3" at 145.03,-33.714 h1.78
  text "4" at 208.699,-33.714 h1.78
  text "5" at 272.174,-33.714 h1.78
  text "6" at 335.801,-33.714 h1.78
M10 Fab Notes:
  drawing of 189 lines, arcs and shapes, not listed
  text "DESIGN INFORMATION" at 314.122,159.826 h1.52
  text "MIN. TRACK WIDTH:" at 297.75,156.469 h1.52
  text "8" at 325.595,156.47 h1.52
  text "MIL" at 329.526,156.469 h1.52
  text "MIN. CLEARANCE:" at 297.75,153.317 h1.52
  text "0.2" at 324.071,153.317 h1.52
  text "mm" at 329.526,153.317 h1.52
  text "MIN. VIA PAD SIZE:" at 297.75,150.164 h1.52
  text "24" at 324.833,150.164 h1.52
  text "MIL" at 329.526,150.164 h1.52
  text "0.05mm (2MIL)" at 315.403,146.864 h1.52
  text "MINIMUM ANNULAR RING" at 289.388,146.656 h1.52
  text "EXTERNAL" at 333.387,146.656 h1.52
  text "PER" at 294.468,143.858 h1.52
  text "IPC-D-275 CLASS 2 LEVEL C" at 300.056,143.858 h1.52
  text "MIL, HOLES" at 337.857,141.306 h1.52
  text "+/-" at 327.889,141.088 h1.52
  text "+/-" at 349.58,141.088 h1.52
  text "REGISTRATION TOLERANCES:" at 289.388,141.061 h1.52
  text "METAL" at 319.862,141.061 h1.52
  text "5" at 334.498,141.061 h1.52
  text "3" at 355.656,141.061 h1.52
  text "MIL" at 358.609,141.061 h1.52
  text "HOLE SIZE TOLERANCE (UNLESS OTHERWISE SPECIFIED):" at 289.388,138.564 h1.52
  text "+/-" at 349.58,138.491 h1.52
  text "3" at 355.656,138.464 h1.52
  text "MIL" at 358.609,138.464 h1.52
  text "MATERIAL:" at 287.489,134.968 h1.52
  text "FR-4 High Tg" at 312.545,131.703 h1.52
  text "X" at 308.876,131.5 h1.52
  text "FR-408" at 298.182,131.385 h1.52
  text "OTHER" at 335.977,131.385 h1.52
  text "62 MIL (1.6mm) +/-10%" at 306.313,127.753 h1.52
  text "X" at 303.262,127.69 h1.52
  text "THICKNESS:" at 289.388,127.544 h1.52
  text "OTHER" at 338.949,127.544 h1.52
  text "TOLERANCE:" at 289.388,124.031 h1.52
  text "X" at 310.933,124.031 h1.52
  text "ANSI IPC-6012 TYPE 3 CLASS 2" at 315.455,124.031 h1.52
  text "OTHER +/-" at 315.454,120.368 h1.52
  text "BOW & TWIST:" at 289.388,116.68 h1.52
  text "X" at 310.933,116.68 h1.52
  text "ANSI IPC-6012 TYPE 3 CLASS 2" at 315.455,116.68 h1.52
  text "OTHER +/-" at 315.454,112.954 h1.52
  text "DRILLING:" at 287.489,109.637 h1.52
  text "NC_DRILL FILES" at 332.218,106.965 h1.52
  text "REFERENCE:" at 289.388,106.865 h1.52
  text "X" at 306.082,106.862 h1.52
  text "AS SHOWN" at 310.603,106.865 h1.52
  text "X" at 328.967,106.865 h1.52
  text "OTHER" at 339.787,103.252 h1.52
  text "PTH COPPER THICKNESS:" at 289.38,103.162 h1.52
  text "X" at 318.316,103.162 h1.52
  text "20-30 um" at 321.567,103.162 h1.52
  text "BOARD FINISH:" at 287.489,99.413 h1.52
  text "SILKSCREEN:" at 291.431,96.616 h1.52
  text "X" at 315.759,96.616 h1.52
  text "TOP" at 318.731,96.616 h1.52
  text "X" at 328.713,96.616 h1.52
  text "BOTTOM" at 331.71,96.616 h1.52
  text "SILKSCREEN COLOR:" at 291.431,92.674 h1.52
  text "X" at 315.734,92.674 h1.52
  text "WHITE" at 318.731,92.674 h1.52
  text "OTHER" at 331.71,92.674 h1.52
  text "X" at 319.061,89.03 h1.52
  text "GREEN" at 322.058,89.03 h1.52
  text "OTHER" at 337.755,89.03 h1.52
  text "SOLDER RESIST COLOR:" at 291.431,88.856 h1.52
  text "X" at 319.061,85.112 h1.52
  text "MATTE" at 322.058,85.112 h1.52
  text "SEMI-GLOSS" at 337.744,85.096 h1.52
  text "IMMERSION GOLD (ENIG)" at 314.438,80.724 h1.52
  text "ENEPIG" at 348.412,80.54 h1.52
  text "SURFACE FINISH:" at 287.489,80.515 h1.52
  text "X" at 309.917,80.515 h1.52
  text "IMM. TIN/SILVER OR EQUIV" at 295.859,77.027 h1.52
  text "OTHER" at 332.218,76.927 h1.52
  text "ARRAY/PANEL:" at 287.489,72.981 h1.52
  text "CUT AND TRIM PER M1 BOARD OUTLINE" at 314.438,72.772 h1.52
  text "N.C. ROUTE" at 314.438,69.318 h1.52
  text "X" at 331.914,69.318 h1.52
  text "V. SCORE" at 336.435,69.318 h1.52
  text "CERTIFICATION:" at 287.489,66.038 h1.52
  text "MATERIALS AND WORKMANSHIP FOR ALL PCBS" at 305.904,66.038 h1.52
  text "TO MEET OR EXCEED THE REQUIREMENTS OF:" at 305.904,63.649 h1.52
  text "X" at 296.697,60.382 h1.52
  text "ANSI IPC-A-600F CLASS ->" at 299.948,60.382 h1.52
  text "X" at 341.807,60.382 h1.52
  text "2" at 344.601,60.382 h1.52
  text "1" at 336.6,60.344 h1.52
  text "3" at 353.592,60.344 h1.52
  text "X" at 317.321,56.631 h1.52
  text "RoHS" at 320.572,56.631 h1.52
  text "OTHER" at 336.94,56.631 h1.52
  text "PER ORDER" at 347.026,56.631 h1.52
  text "ALL BOARDS MUST MEET OR EXCEED UL94-V0 REQUIREMENTS." at 288.188,52.724 h1.52
  text "PCB MUST BEAR THE UL94V-0 UL REGISTERED MATERIAL ID NUMBER" at 288.188,49.776 h1.52
  text "ADDITIONAL REQUIREMENTS:" at 287.489,45.472 h1.52
  text "MICROSECTION:" at 289.388,42.751 h1.52
  text "YES" at 312.394,42.751 h1.52
  text "REQUIRED" at 334.276,39.085 h1.52
  text "BARE BOARD ELEC. TEST:" at 289.388,39.013 h1.52
  text "NONE" at 322.554,39.013 h1.52
  text "X" at 331.279,39.013 h1.52
  text "PER ORDER" at 349.312,39.013 h1.52
  text "XX MIL VIAS REQUIRE NON-CONDUCTIVE FILL AND PLANARIZE" at 293.659,33.807 h1.5
  text "XX MIL VIAS REQUIRE CONDUCTIVE FILL AND PLANARIZE" at 293.862,31.166 h1.52
  text "OUTER XX MIL TRACES REQUIRE 50 OHM SINGLE-ENDED IMPEDANCE" at 293.837,27.016 h1.47
  text "LAYER 2 & 3 (INNER LAYERS) XX MIL WIDE, XX MIL SPACE / TRACES REQUIRE 100 OHM DIFFERENTIAL IMPEDANCE" at 293.634,21.029 h1.52
  text ".Layer_Name" at 14.275,-23.427 h1.52
M11 Gerber Information:
  lines w0.254: -7.798,-25.248 159.842,-25.248 ; -7.798,-20.083 159.893,-20.083 ; -7.798,-14.918 -7.798,-30.412 93.929,-30.412 159.893,-30.412 159.893,-14.918 -7.785,-14.918 -7.785,-30.412 32.233,-30.412 ; 54.813,-30.412 54.813,-14.918 ; 86.995,-20.083 86.995,-14.918 ; 108.331,-20.083 108.331,-14.918 ; 124.13,-30.577 124.13,-25.425
  text "ALL ARTWORK VIEWED FROM TOP SIDE" at -6.185,-18.275 h1.52
  text "BOARD #:" at 56.718,-18.275 h1.52
  text ".PRJ_Number" at 70.574,-18.275 h1.52
  text "REV:" at 92.024,-18.275 h1.52
  text ".PCB_Rev" at 99.428,-18.275 h1.52
  text "SVN REV:" at 113.309,-18.275 h1.52
  text ".VersionControl_RevNumber" at 126.162,-18.275 h1.52
  text "LAYER NAME =" at -6.185,-23.427 h1.52
  text "TID #:" at 56.718,-23.44 h1.52
  text ".TID" at 70.574,-23.44 h1.52
  text "PLOT NAME =" at -6.185,-28.655 h1.52
  text ".plot_File_Name" at 14.275,-28.655 h1.52
  text "GENERATED    :" at 56.769,-28.655 h1.52
  text ".Print_Date" at 78.854,-28.655 h1.52
  text ".Print_Time" at 97.371,-28.655 h1.52
  text "TEXAS INSTRUMENTS" at 129.489,-28.655 h1.52
M12 Stackup:
  drawing of 295 lines, arcs and shapes, not listed
  text "Layer" at 248.738,192.689 h1.52
  text "Name" at 259.15,192.689 h1.52
  text "Material" at 282.765,192.689 h1.52
  text "Thickness" at 304.604,192.689 h1.52
  text "Constant" at 321.109,192.689 h1.52
  text "Board Layer Stack" at 335.584,192.689 h1.52
  text "Top Overlay" at 259.15,189.641 h1.52
  text "Top Solder" at 259.15,186.593 h1.52
  text "Solder Resist" at 282.765,186.593 h1.52
  text "7,09mil" at 304.604,186.593 h1.52
  text "3.5" at 321.109,186.593 h1.52
  text "1" at 248.738,183.545 h1.52
  text "Top Layer" at 259.15,183.545 h1.52
  text "2,76mil" at 304.604,183.545 h1.52
  text "Dielectric1" at 259.15,180.497 h1.52
  text "FR-4" at 282.765,180.497 h1.52
  text "9,13mil" at 304.604,180.497 h1.52
  text "4.8" at 321.109,180.497 h1.52
  text "2" at 248.738,177.449 h1.52
  text "Mid-Layer 1" at 259.15,177.449 h1.52
  text "1,40mil" at 304.604,177.449 h1.52
  text "Dielectric2" at 259.15,174.401 h1.52
  text "FR-4" at 282.765,174.401 h1.52
  text "27,95mil" at 304.604,174.401 h1.52
  text "4.8" at 321.109,174.401 h1.52
  text "3" at 248.738,171.353 h1.52
  text "Mid-Layer 2" at 259.15,171.353 h1.52
  text "1,40mil" at 304.604,171.353 h1.52
  text "Dielectric3" at 259.15,168.305 h1.52
  text "FR-4" at 282.765,168.305 h1.52
  text "12,60mil" at 304.604,168.305 h1.52
  text "4.8" at 321.109,168.305 h1.52
  text "4" at 248.738,165.257 h1.52
  text "Bottom Layer" at 259.15,165.257 h1.52
  text "2,76mil" at 304.604,165.257 h1.52
  text "Bottom Solder" at 259.15,162.209 h1.52
  text "Solder Resist" at 282.765,162.209 h1.52
  text "0,71mil" at 304.604,162.209 h1.52
  text "3.5" at 321.109,162.209 h1.52
  text "Bottom Overlay" at 259.15,159.161 h1.52
  text ".Layer_Name" at 14.275,-23.427 h1.52
M13 Component Bodies Top:
  text ".Layer_Name" at 14.275,-23.427 h1.52
M14 Component Bodies Bottom:
  text ".Layer_Name" at 14.275,-23.427 h1.52
M15 Courtyards Top:
  text ".Layer_Name" at 14.275,-23.427 h1.52
M16 Courtyards Bottom:
  text ".Layer_Name" at 14.275,-23.427 h1.52
Drill Drawing:
  drawing of 184 lines, arcs and shapes, not listed
  text "Symbol" at 158.037,193.792 h1.83
  text "Quantity" at 165.671,193.792 h1.83
  text "Finished Hole Size" at 174.104,193.792 h1.83
  text "Plated" at 190.272,193.792 h1.83
  text "Hole Type" at 196.855,193.792 h1.83
  text "Drill Layer Pair" at 206.384,193.792 h1.83
  text "Hole Tolerance" at 224.782,193.792 h1.83
  text "9" at 165.671,190.634 h1.52
  text "11,81mil (0,300mm)" at 174.104,190.634 h1.52
  text "PTH" at 190.272,190.634 h1.52
  text "Round" at 196.855,190.634 h1.52
  text "Top Layer - Bottom Layer" at 206.384,190.634 h1.52
  text "F" at 157.394,190.381 h1.4
  text "70" at 165.671,187.477 h1.52
  text "15,00mil (0,381mm)" at 174.104,187.477 h1.52
  text "PTH" at 190.272,187.477 h1.52
  text "Round" at 196.855,187.477 h1.52
  text "Top Layer - Bottom Layer" at 206.384,187.477 h1.52
  text "E" at 157.394,187.223 h1.4
  text "6" at 165.671,184.319 h1.52
  text "15,75mil (0,400mm)" at 174.104,184.319 h1.52
  text "PTH" at 190.272,184.319 h1.52
  text "Round" at 196.855,184.319 h1.52
  text "Top Layer - Bottom Layer" at 206.384,184.319 h1.52
  text "G" at 157.394,184.065 h1.4
  text "30" at 165.671,181.161 h1.52
  text "19,69mil (0,500mm)" at 174.104,181.161 h1.52
  text "PTH" at 190.272,181.161 h1.52
  text "Round" at 196.855,181.161 h1.52
  text "Top Layer - Bottom Layer" at 206.384,181.161 h1.52
  text "H" at 157.394,180.908 h1.4
  text "8" at 165.671,178.004 h1.52
  text "25,59mil (0,650mm)" at 174.104,178.004 h1.52
  text "PTH" at 190.272,178.004 h1.52
  text "Round" at 196.855,178.004 h1.52
  text "Top Layer - Bottom Layer" at 206.384,178.004 h1.52
  text "2" at 165.671,174.846 h1.52
  text "33,47mil (0,850mm)" at 174.104,174.846 h1.52
  text "PTH" at 190.272,174.846 h1.52
  text "Round" at 196.855,174.846 h1.52
  text "Top Layer - Bottom Layer" at 206.384,174.846 h1.52
  text "B" at 157.394,174.592 h1.4
  text "24" at 165.671,171.688 h1.52
  text "35,43mil (0,900mm)" at 174.104,171.688 h1.52
  text "PTH" at 190.272,171.688 h1.52
  text "Round" at 196.855,171.688 h1.52
  text "Top Layer - Bottom Layer" at 206.384,171.688 h1.52
  text "2" at 165.671,168.53 h1.52
  text "39,37mil (1,000mm)" at 174.104,168.53 h1.52
  text "PTH" at 190.272,168.53 h1.52
  text "Round" at 196.855,168.53 h1.52
  text "Top Layer - Bottom Layer" at 206.384,168.53 h1.52
  text "+3,94mil/-0,00mil" at 224.782,168.53 h1.52
  text "10" at 165.671,165.373 h1.52
  text "39,37mil (1,000mm)" at 174.104,165.373 h1.52
  text "PTH" at 190.272,165.373 h1.52
  text "Round" at 196.855,165.373 h1.52
  text "Top Layer - Bottom Layer" at 206.384,165.373 h1.52
  text "4" at 165.671,162.215 h1.52
  text "41,34mil (1,050mm)" at 174.104,162.215 h1.52
  text "PTH" at 190.272,162.215 h1.52
  text "Round" at 196.855,162.215 h1.52
  text "Top Layer - Bottom Layer" at 206.384,162.215 h1.52
  text "4" at 165.671,159.057 h1.52
  text "43,31mil (1,100mm)" at 174.104,159.057 h1.52
  text "PTH" at 190.272,159.057 h1.52
  text "Round" at 196.855,159.057 h1.52
  text "Top Layer - Bottom Layer" at 206.384,159.057 h1.52
  text "24" at 165.671,155.899 h1.52
  text "45,28mil (1,150mm)" at 174.104,155.899 h1.52
  text "PTH" at 190.272,155.899 h1.52
  text "Round" at 196.855,155.899 h1.52
  text "Top Layer - Bottom Layer" at 206.384,155.899 h1.52
  text "5" at 165.671,152.742 h1.52
  text "49,21mil (1,250mm)" at 174.104,152.742 h1.52
  text "PTH" at 190.272,152.742 h1.52
  text "Round" at 196.855,152.742 h1.52
  text "Top Layer - Bottom Layer" at 206.384,152.742 h1.52
  text "12" at 165.671,149.584 h1.52
  text "50,00mil (1,270mm)" at 174.104,149.584 h1.52
  text "PTH" at 190.272,149.584 h1.52
  text "Round" at 196.855,149.584 h1.52
  text "Top Layer - Bottom Layer" at 206.384,149.584 h1.52
  text "4" at 165.671,146.426 h1.52
  text "51,18mil (1,300mm)" at 174.104,146.426 h1.52
  text "PTH" at 190.272,146.426 h1.52
  text "Round" at 196.855,146.426 h1.52
  text "Top Layer - Bottom Layer" at 206.384,146.426 h1.52
  text "A" at 157.394,146.173 h1.4
  text "14" at 165.671,143.269 h1.52
  text "53,15mil (1,350mm)" at 174.104,143.269 h1.52
  text "PTH" at 190.272,143.269 h1.52
  text "Round" at 196.855,143.269 h1.52
  text "Top Layer - Bottom Layer" at 206.384,143.269 h1.52
  text "C" at 157.394,143.015 h1.4
  text "4" at 165.671,140.111 h1.52
  text "55,12mil (1,400mm)" at 174.104,140.111 h1.52
  text "PTH" at 190.272,140.111 h1.52
  text "Round" at 196.855,140.111 h1.52
  text "Top Layer - Bottom Layer" at 206.384,140.111 h1.52
  text "4" at 165.671,136.953 h1.52
  text "59,06mil (1,500mm)" at 174.104,136.953 h1.52
  text "PTH" at 190.272,136.953 h1.52
  text "Round" at 196.855,136.953 h1.52
  text "Top Layer - Bottom Layer" at 206.384,136.953 h1.52
  text "8" at 165.671,133.795 h1.52
  text "62,99mil (1,600mm)" at 174.104,133.795 h1.52
  text "PTH" at 190.272,133.795 h1.52
  text "Round" at 196.855,133.795 h1.52
  text "Top Layer - Bottom Layer" at 206.384,133.795 h1.52
  text "+/-3,00mil" at 224.782,133.795 h1.52
  text "6" at 165.671,130.638 h1.52
  text "78,74mil (2,000mm)" at 174.104,130.638 h1.52
  text "PTH" at 190.272,130.638 h1.52
  text "Round" at 196.855,130.638 h1.52
  text "Top Layer - Bottom Layer" at 206.384,130.638 h1.52
  text "16" at 165.671,127.48 h1.52
  text "80,00mil (2,032mm)" at 174.104,127.48 h1.52
  text "PTH" at 190.272,127.48 h1.52
  text "Round" at 196.855,127.48 h1.52
  text "Top Layer - Bottom Layer" at 206.384,127.48 h1.52
  text "+/-3,00mil" at 224.782,127.48 h1.52
  text "2" at 165.671,124.322 h1.52
  text "98,43mil (2,500mm)" at 174.104,124.322 h1.52
  text "PTH" at 190.272,124.322 h1.52
  text "Round" at 196.855,124.322 h1.52
  text "Top Layer - Bottom Layer" at 206.384,124.322 h1.52
  text "D" at 157.394,124.068 h1.4
  text "2" at 165.671,121.164 h1.52
  text "106,30mil (2,700mm)" at 174.104,121.164 h1.52
  text "PTH" at 190.272,121.164 h1.52
  text "Round" at 196.855,121.164 h1.52
  text "Top Layer - Bottom Layer" at 206.384,121.164 h1.52
  text "270 Total" at 165.671,118.007 h1.52
  text ".Layer_Name" at 14.275,-23.427 h1.52
M17 Embedded Cavity:
  text ".Layer_Name" at 14.275,-23.427 h1.52
M18 Embedded Assembly:
  text ".Layer_Name" at 14.275,-23.427 h1.52
M19 Embedded Keepout:
  text ".Layer_Name" at 14.275,-23.427 h1.52

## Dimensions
-0.381,-11.781 to 25.019,-11.781 on M2 Board Dimensions
0,0 to 0,102.265 on M2 Board Dimensions
0,0 to 218.44,0.069 on M2 Board Dimensions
